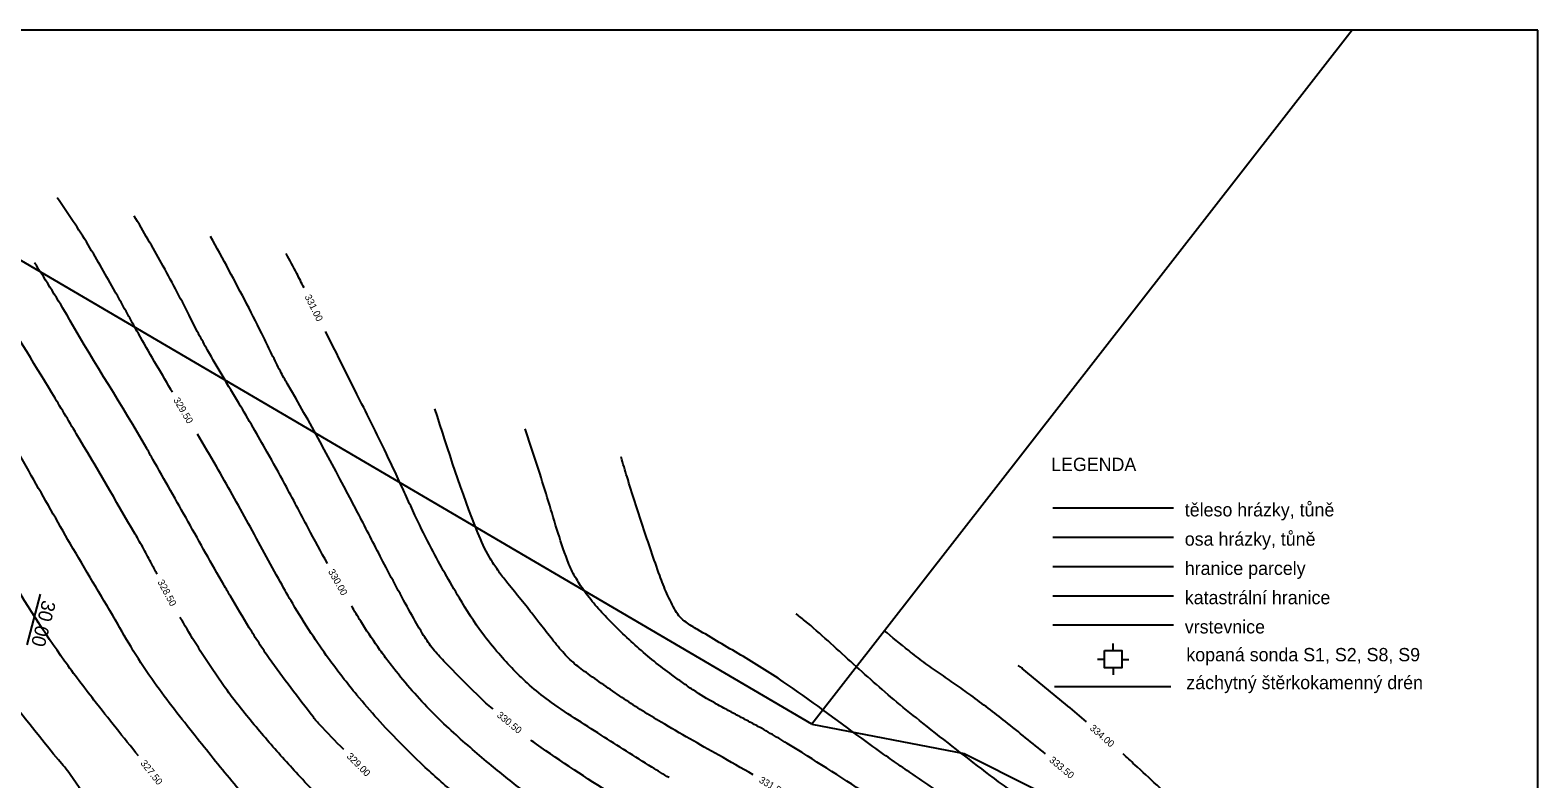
# Model space of a CAD drawing. Extents: x -564043 to -563833, y -1163561 to -1163412.
# Drawn here: x -563941.2 to -563833, y -1163466.2 to -1163412.5 of the extents above; entities that cross this region are included whole.
import ezdxf

# ---------------------------------------------------------------- set-up
doc = ezdxf.new("R2010")
doc.units = 0
for name, color, linetype in [('_popis staničení T1', 7, 'Continuous'), ('_rám PH1 a PH3', 7, 'Continuous'), ('Hranice parcel', 7, 'Continuous'), ('Obvod PU', 7, 'Continuous'), ('Vrstva 24', 7, 'Continuous'), ('Vrstva 25', 7, 'Continuous'), ('Vrstva 26', 7, 'Continuous')]:
    doc.layers.add(name, color=color, linetype=linetype)

msp = doc.modelspace()

# ---------------------------------------------------------------- linework, layer by layer
at = {"layer": '_popis staničení T1'}
msp.add_line((-563941.44, -1163456.61), (-563940.5, -1163452.97), dxfattribs=at)
at = {"layer": '_rám PH1 a PH3'}
for p, q in [((-563833.05, -1163412.49), (-564043.05, -1163412.49)), ((-563833.05, -1163560.99), (-563833.05, -1163412.49)), ((-563867.84, -1163446.79), (-563859.19, -1163446.79)), ((-563867.84, -1163448.89), (-563859.19, -1163448.89)), ((-563867.84, -1163450.99), (-563859.19, -1163450.99)), ((-563867.84, -1163453.09), (-563859.19, -1163453.09)), ((-563867.84, -1163455.19), (-563859.19, -1163455.19)), ((-563863.52, -1163457.03), (-563863.52, -1163456.53)), ((-563864.14, -1163457.68), (-563864.64, -1163457.68)), ((-563863.53, -1163458.28), (-563863.53, -1163458.78)), ((-563862.89, -1163457.66), (-563862.39, -1163457.66)), ((-563867.74, -1163459.61), (-563859.37, -1163459.61))]:
    msp.add_line(p, q, dxfattribs=at)
msp.add_lwpolyline([(-563864.14, -1163457.03), (-563862.89, -1163457.03), (-563862.89, -1163458.28), (-563864.14, -1163458.28)], close=True, dxfattribs=at)
at = {"layer": 'Hranice parcel'}
msp.add_lwpolyline([(-563885.14, -1163462.32), (-563943.67, -1163427.99), (-563964.47, -1163416.08)], dxfattribs=at)
at = {"layer": 'Obvod PU'}
for points in [[(-563846.38, -1163412.49), (-563885.14, -1163462.32)], [(-563885.14, -1163462.32), (-563874.2, -1163464.42), (-563869.21, -1163466.93)]]:
    msp.add_lwpolyline(points, dxfattribs=at)
at = {"layer": 'Vrstva 24'}
for points in [[(-563918.73, -1163464.14), (-563920.47, -1163462.33), (-563920.75, -1163462.02), (-563920.93, -1163461.79), (-563924.08, -1163457.59), (-563924.81, -1163456.5), (-563925.51, -1163455.39), (-563926.86, -1163453.13), (-563927.09, -1163452.73), (-563927.34, -1163452.3), (-563929.89, -1163447.79), (-563932.42, -1163443.31), (-563932.86, -1163442.53), (-563938.36, -1163433.35), (-563938.44, -1163433.21), (-563940.92, -1163429.19)], [(-563921.58, -1163430.99), (-563922.1, -1163429.96), (-563922.86, -1163428.53)], [(-563895.38, -1163466.15), (-563896.62, -1163465.4), (-563900.27, -1163463.09), (-563904.04, -1163460.59), (-563905.39, -1163459.51), (-563907.61, -1163457.24), (-563908.76, -1163455.82), (-563910.43, -1163453.26), (-563912.44, -1163449.7), (-563913.55, -1163447.46), (-563914.15, -1163446.16), (-563914.75, -1163444.86), (-563915.97, -1163442.27), (-563917.91, -1163438.37), (-563920.03, -1163434.12)], [(-563881.22, -1163467.31), (-563886.92, -1163463.69), (-563888.12, -1163462.97), (-563888.75, -1163462.61), (-563889.58, -1163462.16), (-563890.42, -1163461.71), (-563891.25, -1163461.27), (-563892.09, -1163460.81), (-563893.67, -1163459.85), (-563894.43, -1163459.32), (-563895.18, -1163458.78), (-563896.46, -1163457.8), (-563897.67, -1163456.77), (-563898.84, -1163455.68), (-563899.98, -1163454.54), (-563900.9, -1163453.5), (-563901.73, -1163452.38), (-563902.04, -1163451.88), (-563902.33, -1163451.36), (-563902.78, -1163450.28), (-563904.21, -1163445.76), (-563905.71, -1163441.12)], [(-563919.38, -1163476.01), (-563920.12, -1163475.14), (-563923.22, -1163471.06), (-563923.7, -1163470.36), (-563924.16, -1163469.69), (-563926.77, -1163466.4), (-563928.09, -1163464.78), (-563929.4, -1163463.14), (-563932.31, -1163459.34), (-563933.83, -1163457.04), (-563935.11, -1163454.85), (-563938.34, -1163449.38), (-563939.75, -1163446.92), (-563941.15, -1163444.46), (-563942.64, -1163441.76)], [(-563862.95, -1163472.88), (-563865.36, -1163470.94), (-563867.28, -1163469.56), (-563868.39, -1163468.78), (-563869.51, -1163468), (-563870.63, -1163467.22), (-563871.74, -1163466.44), (-563872.34, -1163465.99), (-563877.17, -1163462.24), (-563879.04, -1163460.73), (-563880.71, -1163459.29), (-563882.35, -1163457.82), (-563883.98, -1163456.34), (-563885.65, -1163454.89), (-563886.03, -1163454.58), (-563886.15, -1163454.49), (-563886.22, -1163454.45), (-563886.25, -1163454.42), (-563886.27, -1163454.41)], [(-563941.26, -1163493.01), (-563939, -1163490.7), (-563935.17, -1163486.58), (-563933.6, -1163484.77), (-563933.04, -1163483.79), (-563932.45, -1163481.94), (-563932.39, -1163481.58), (-563932.34, -1163479.09), (-563932.36, -1163478.88), (-563932.37, -1163478.7), (-563932.36, -1163477.98), (-563932.29, -1163477.27), (-563932.23, -1163476.55), (-563932.24, -1163475.83), (-563932.27, -1163475.75), (-563932.33, -1163475.65), (-563935.19, -1163471.03), (-563938.35, -1163465.93), (-563938.45, -1163465.79), (-563938.86, -1163465.28), (-563944.23, -1163458.58)], [(-563865.43, -1163462.14), (-563866.77, -1163461.01), (-563870.02, -1163458.33), (-563870.14, -1163458.23), (-563870.19, -1163458.19), (-563870.34, -1163458.09)], [(-563834.56, -1163494.64), (-563836.37, -1163491.68), (-563837.26, -1163490.4), (-563838.09, -1163489.32), (-563838.93, -1163488.26), (-563840.68, -1163486.18), (-563843.6, -1163482.93), (-563845.38, -1163480.99), (-563847.69, -1163478.52), (-563848.87, -1163477.31), (-563850.08, -1163476.13), (-563853.18, -1163473.26), (-563856.32, -1163470.43), (-563856.74, -1163470.06), (-563856.9, -1163469.93), (-563857.18, -1163469.67), (-563858.78, -1163468.19), (-563860.37, -1163466.7), (-563861.97, -1163465.22), (-563862.81, -1163464.45)]]:
    msp.add_spline(points, degree=3, dxfattribs=at)
at = {"layer": 'Vrstva 25'}
for points in [[(-563919.9, -1163450.79), (-563921.28, -1163448.23), (-563922.95, -1163445.09), (-563924.22, -1163442.79), (-563926.26, -1163439.27), (-563928.5, -1163435.47), (-563929.15, -1163434.28), (-563929.83, -1163432.95), (-563931.81, -1163429.21), (-563933.77, -1163425.82)], [(-563887.06, -1163480.68), (-563889.48, -1163478.12), (-563890.68, -1163477.11), (-563891.26, -1163476.71), (-563892.36, -1163476), (-563898.34, -1163472.15), (-563901.29, -1163470.25), (-563905.74, -1163467.17), (-563908.13, -1163465.28), (-563910.84, -1163462.93), (-563912.22, -1163461.62), (-563914.97, -1163458.53), (-563915.64, -1163457.66), (-563916.29, -1163456.77), (-563917.51, -1163454.93), (-563918.17, -1163453.84)]]:
    msp.add_spline(points, degree=3, dxfattribs=at)
at = {"layer": 'Vrstva 26'}
for points in [[(-563932.12, -1163451.55), (-563932.51, -1163450.83), (-563933.08, -1163449.75), (-563933.69, -1163448.68), (-563937.9, -1163441.49), (-563939.67, -1163438.54), (-563943.81, -1163431.76), (-563944.65, -1163430.42), (-563945.42, -1163429.3), (-563947.84, -1163425.66), (-563950.04, -1163421.85), (-563951.29, -1163419.54), (-563951.84, -1163418.69), (-563952.5, -1163417.84), (-563953.82, -1163416.23)], [(-563931.02, -1163438.49), (-563931.13, -1163438.3), (-563933.46, -1163434.28), (-563933.88, -1163433.53), (-563934.3, -1163432.77), (-563934.71, -1163432.02), (-563935.13, -1163431.27), (-563937.07, -1163427.91), (-563938.14, -1163426.22), (-563939.3, -1163424.52)], [(-563908.01, -1163461.23), (-563908.06, -1163461.19), (-563909.84, -1163459.52), (-563911.55, -1163457.78), (-563912.31, -1163456.93), (-563913, -1163455.94), (-563913.8, -1163454.56), (-563915.81, -1163450.84), (-563917.45, -1163447.66), (-563918.16, -1163446.3), (-563922.78, -1163437.87), (-563923.03, -1163437.44), (-563923.28, -1163436.98), (-563923.88, -1163435.77), (-563924.47, -1163434.56), (-563925.68, -1163432.16), (-563928.28, -1163427.3)], [(-563933.46, -1163464.59), (-563936.66, -1163460.58), (-563938.76, -1163457.78), (-563942.84, -1163451.43), (-563944.76, -1163447.97), (-563948.45, -1163440.73), (-563949, -1163439.65), (-563949.55, -1163438.67), (-563950.17, -1163437.66), (-563950.81, -1163436.67), (-563951.44, -1163435.67), (-563952.06, -1163434.65), (-563954.29, -1163430.74), (-563955.08, -1163429.28)], [(-563889.36, -1163465.94), (-563891.82, -1163464.54), (-563895.95, -1163462.17), (-563898.61, -1163460.5), (-563899.91, -1163459.61), (-563901.2, -1163458.7), (-563902.16, -1163457.97), (-563902.61, -1163457.57), (-563903.02, -1163457.13), (-563903.88, -1163456.08), (-563904.72, -1163455.02), (-563905.32, -1163454.24), (-563907.18, -1163451.93), (-563907.75, -1163451.15), (-563908.02, -1163450.74), (-563908.28, -1163450.32), (-563909.1, -1163448.57), (-563912.19, -1163439.67)], [(-563903.21, -1163473.11), (-563903.34, -1163473.04), (-563904.67, -1163472.17), (-563906.5, -1163470.85), (-563910.71, -1163467.34), (-563913.03, -1163465.28), (-563914.75, -1163463.59), (-563917.78, -1163460.23), (-563919.82, -1163457.6), (-563921.06, -1163455.8), (-563922.39, -1163453.66), (-563923.26, -1163452.13), (-563925.57, -1163447.92), (-563926.72, -1163445.85), (-563927.87, -1163443.82), (-563929.22, -1163441.49)], [(-563871.86, -1163470.11), (-563873.03, -1163469.28), (-563875.16, -1163467.79), (-563876.36, -1163466.96), (-563877.56, -1163466.14), (-563878.77, -1163465.32), (-563879.97, -1163464.48), (-563881.54, -1163463.35), (-563887.19, -1163459.27), (-563890.24, -1163457.35), (-563891.79, -1163456.44), (-563893.34, -1163455.52), (-563894.17, -1163455), (-563894.59, -1163454.63), (-563894.92, -1163454.18), (-563895.24, -1163453.56), (-563895.54, -1163452.93), (-563896.06, -1163451.64), (-563896.67, -1163449.88), (-563897.27, -1163448.11), (-563898.4, -1163444.56), (-563898.83, -1163443.13)], [(-563945.26, -1163485.58), (-563942.43, -1163481.61), (-563942.36, -1163481.51), (-563941.86, -1163480.72), (-563941.1, -1163479.34), (-563940.18, -1163477.03), (-563940.14, -1163476.81), (-563940.11, -1163476.58), (-563939.74, -1163474.25), (-563939.83, -1163473.92), (-563940.07, -1163473.54), (-563942.89, -1163468.84), (-563943.52, -1163467.68), (-563944.1, -1163466.49), (-563944.69, -1163465.31), (-563945.31, -1163464.14), (-563945.97, -1163463.14), (-563948.42, -1163460.21), (-563952.01, -1163455.85), (-563952.99, -1163454.39), (-563953.59, -1163453.33), (-563954.16, -1163452.26), (-563954.74, -1163451.18), (-563955.25, -1163450.27)], [(-563905.62, -1163487.17), (-563905.71, -1163486.43), (-563906.14, -1163484.4), (-563906.33, -1163483.59), (-563906.62, -1163482.77), (-563906.83, -1163482.38), (-563907.08, -1163482.01), (-563907.56, -1163481.45), (-563908.07, -1163480.92), (-563908.73, -1163480.27), (-563912.1, -1163476.61), (-563915.34, -1163473.08), (-563915.91, -1163472.42), (-563916.76, -1163471.47), (-563918.06, -1163470.07), (-563919.38, -1163468.7), (-563920.7, -1163467.33), (-563922, -1163465.94), (-563924.22, -1163463.46), (-563925.29, -1163462.19), (-563926.34, -1163460.89), (-563927.35, -1163459.54), (-563928.17, -1163458.34), (-563930.36, -1163454.82), (-563930.46, -1163454.64)], [(-563868.37, -1163464.45), (-563871.25, -1163462.13), (-563873.73, -1163460.24), (-563874.85, -1163459.44), (-563875.98, -1163458.66), (-563877.1, -1163457.87), (-563878.19, -1163457.03), (-563879.96, -1163455.58)], [(-563873.45, -1163489.45), (-563873.73, -1163488.98), (-563874.78, -1163487.44), (-563876.78, -1163484.89), (-563881.14, -1163480.24), (-563883.66, -1163478.01), (-563887.51, -1163475.07), (-563890.54, -1163473.02), (-563896.23, -1163469.44), (-563897.37, -1163468.71), (-563897.94, -1163468.34), (-563899.48, -1163467.35), (-563904.89, -1163463.75), (-563905.31, -1163463.45)]]:
    msp.add_spline(points, degree=3, dxfattribs=at)

# ---------------------------------------------------------------- texts
at = {"layer": '_popis staničení T1'}
msp.add_text('30.00', height=1, rotation=255.5058, dxfattribs=at).set_placement((-563940.34, -1163453.35))
at = {"layer": '_rám PH1 a PH3'}
for s, p in [('LEGENDA', (-563867.97, -1163444.14)), ('těleso hrázky, tůně', (-563858.38, -1163447.4)), ('osa hrázky, tůně', (-563858.38, -1163449.5)), ('hranice parcely', (-563858.38, -1163451.6)), ('katastrální hranice', (-563858.38, -1163453.7)), ('vrstevnice', (-563858.38, -1163455.8)), ('kopaná sonda S1, S2, S8, S9', (-563858.27, -1163457.8)), ('záchytný štěrkokamenný drén', (-563858.27, -1163459.8))]:
    msp.add_text(s, height=0.956, rotation=360, dxfattribs=at).set_placement(p)
at = {"layer": 'Vrstva 25'}
for s, rotation, p in [('331.00', 296.3844, (-563921.55, -1163431.62)), ('329.50', 300.895, (-563930.98, -1163439.04)), ('328.50', 298.2595, (-563932.11, -1163452.1)), ('330.00', 299.4755, (-563919.87, -1163451.35)), ('330.50', 320.8421, (-563907.79, -1163461.74)), ('334.00', 318.7306, (-563865.24, -1163462.66)), ('327.50', 308.6467, (-563933.35, -1163465.13)), ('329.00', 314.6992, (-563918.56, -1163464.66)), ('333.50', 320.2433, (-563868.15, -1163464.96)), ('331.50', 329.5681, (-563888.98, -1163466.46))]:
    msp.add_text(s, height=0.5, rotation=rotation, dxfattribs=at).set_placement(p)

doc.saveas('drawing.dxf')
